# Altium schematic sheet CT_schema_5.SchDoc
size 277 x 170 mm
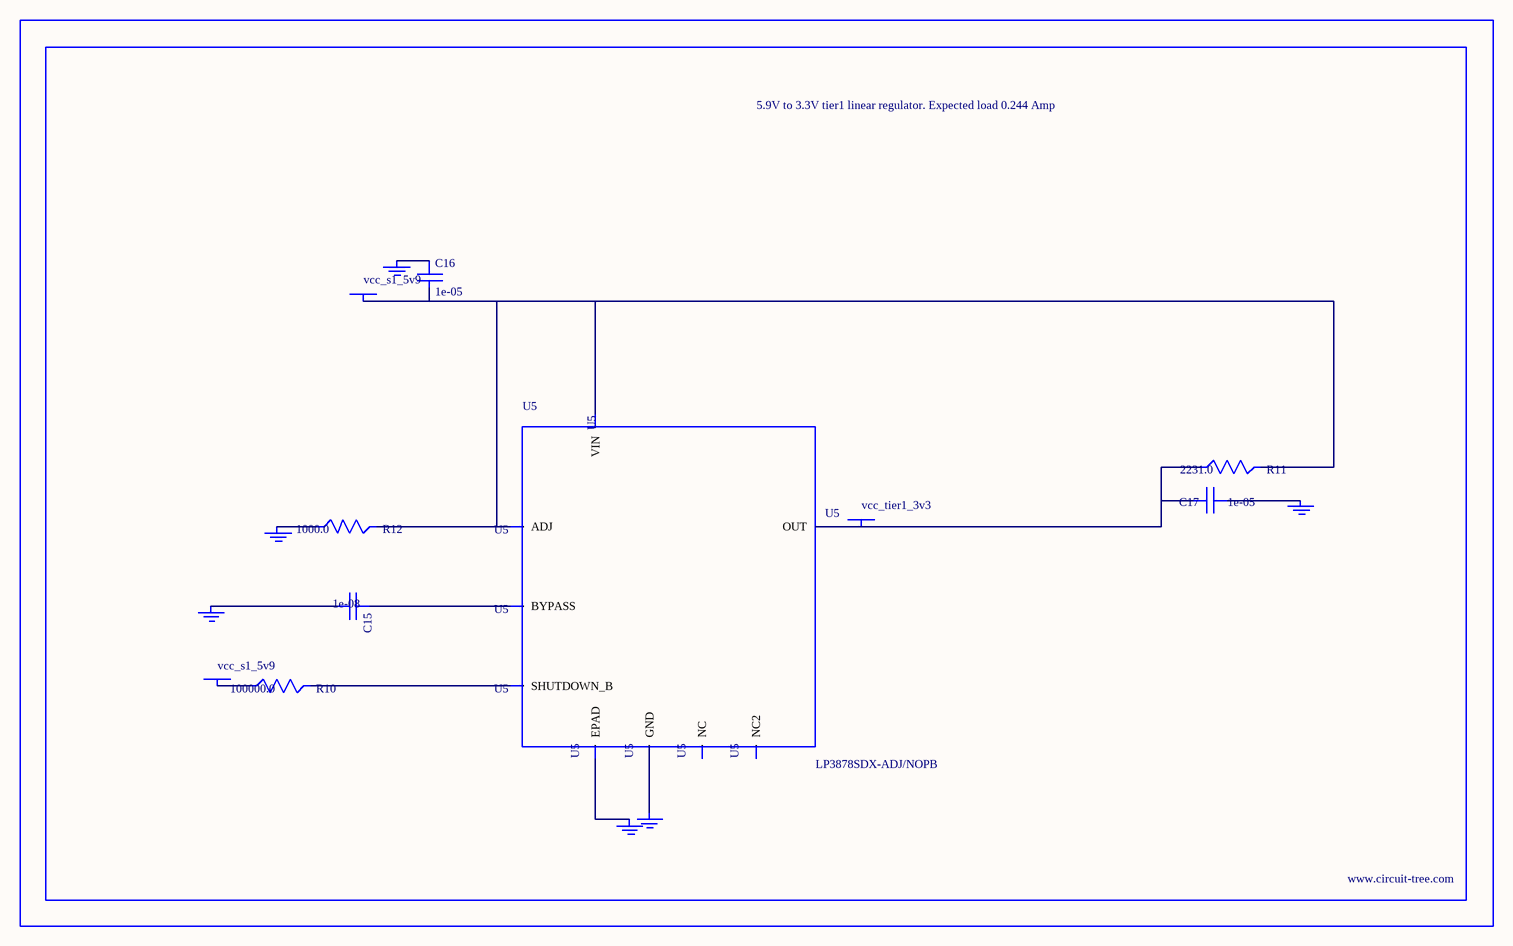
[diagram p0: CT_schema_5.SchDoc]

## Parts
BORDER4  (no value)
C15  1e-08  [C0402]
C16  1e-05  [C1206]
C17  1e-05  [C1210]
GND_INSTANCE_4_0  (no value)
GND_INSTANCE_4_1  (no value)
GND_INSTANCE_4_2  (no value)
GND_INSTANCE_4_3  (no value)
GND_INSTANCE_4_4  (no value)
GND_INSTANCE_4_5  (no value)
POWER_INSTANCE_4_0  vcc_s1_5v9
POWER_INSTANCE_4_1  vcc_s1_5v9
POWER_INSTANCE_4_2  vcc_tier1_3v3
R10  100000.0  [R0603]
R11  2231.0  [R0603]
R12  1000.0  [R0603]
U5  LP3878SDX-ADJ/NOPB  [WSON-8]

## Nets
NetC15_1: C15.1 U5.1(BYPASS)
NetC15_2: C15.2 GND_INSTANCE_4_0.0(GND)
NetC16_1: C16.1 GND_INSTANCE_4_1.0(GND)
NetC16_2: C16.2 POWER_INSTANCE_4_0.0(PWR) R11.2 R12.2 U5.4(VIN) U5.6(ADJ)
NetC17_1: C17.1 GND_INSTANCE_4_2.0(GND)
NetC17_2: C17.2 POWER_INSTANCE_4_2.0(PWR) R11.1 U5.5(OUT)
NetGND_INSTANCE_4_3_0: GND_INSTANCE_4_3.0(GND) R12.1
NetGND_INSTANCE_4_4_0: GND_INSTANCE_4_4.0(GND) U5.PAD(EPAD)
NetGND_INSTANCE_4_5_0: GND_INSTANCE_4_5.0(GND) U5.3(GND)
NetPOWER_INSTANCE_4_1_0: POWER_INSTANCE_4_1.0(PWR) R10.1
NetR10_2: R10.2 U5.8(SHUTDOWN_B)

Not connected (* = marked no-connect by the designer): U5 2(NC) 7(NC2)

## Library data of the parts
BORDER4 = BORDER_PAGE4
C15 = C0402C103K3RAC
C16 = C1206C106K3RACTU
C17 = GRM32DR61E106MA12L
GND_INSTANCE_4_0-GND_INSTANCE_4_5 = GND
POWER_INSTANCE_4_0-POWER_INSTANCE_4_2 = PWR
R10 = RC0603JR-07100KL
R11 = R11
R12 = RC0603JR-071KL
